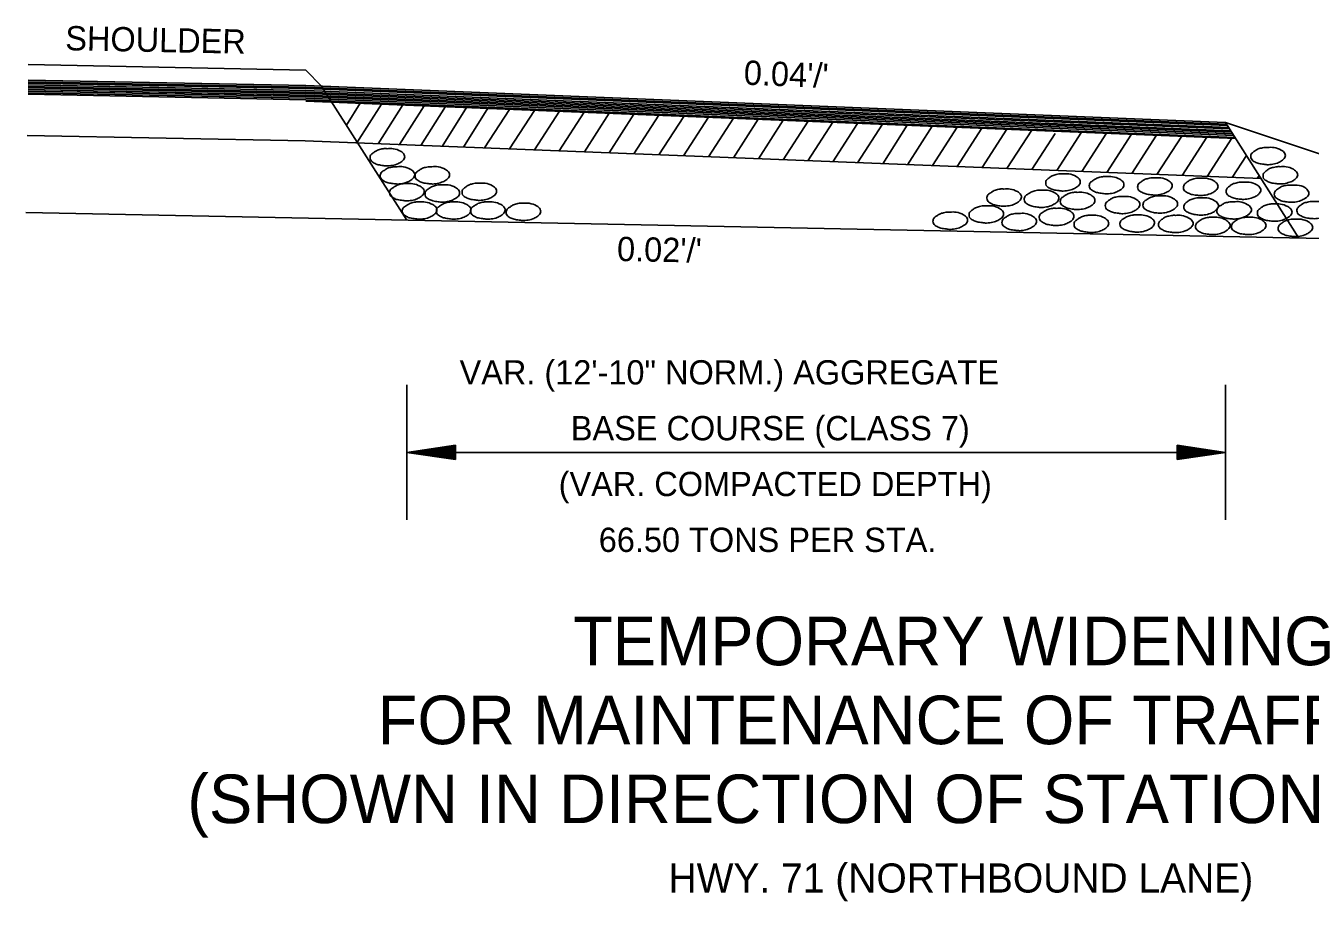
# Model space of a CAD drawing. Extents: x 634177 to 635904, y 289936 to 290970.
# Drawn here: x 635651.94 to 635683.67, y 290816.59 to 290838.23 of the extents above; entities that cross this region are included whole.
import ezdxf

# ---------------------------------------------------------------- set-up
doc = ezdxf.new("R2010")
doc.units = 0
doc.layers.add('Default', color=7, linetype='Continuous')

msp = doc.modelspace()

# ---------------------------------------------------------------- linework, layer by layer
at = {"layer": 'Default'}
for p, q in [((635651.994, 290836.882), (635658.855, 290836.747)), ((635651.994, 290836.84), (635658.855, 290836.703)), ((635651.994, 290836.808), (635658.855, 290836.67)), ((635651.994, 290836.767), (635658.855, 290836.628)), ((635651.994, 290836.727), (635658.855, 290836.586)), ((635658.855, 290836.747), (635681.573, 290835.834)), ((635659.246, 290836.733), (635661.351, 290833.421)), ((635651.994, 290836.689), (635658.855, 290836.55)), ((635651.994, 290836.65), (635658.855, 290836.512)), ((635651.994, 290836.611), (635658.855, 290836.474)), ((635651.994, 290836.568), (635658.855, 290836.432)), ((635651.994, 290836.53), (635658.855, 290836.395)), ((635658.855, 290836.703), (635681.601, 290835.789)), ((635658.855, 290836.67), (635681.619, 290835.761)), ((635658.855, 290836.628), (635681.649, 290835.714)), ((635658.855, 290836.586), (635681.674, 290835.675)), ((635658.855, 290836.55), (635681.703, 290835.629)), ((635658.855, 290836.512), (635681.724, 290835.596)), ((635658.855, 290836.474), (635681.752, 290835.551)), ((635658.855, 290836.432), (635681.777, 290835.512)), ((635658.855, 290836.395), (635681.806, 290835.466)), ((635658.855, 290836.362), (635681.823, 290835.44)), ((635659.857, 290835.772), (635660.198, 290836.311)), ((635660.114, 290835.329), (635660.722, 290836.289)), ((635660.639, 290835.308), (635661.248, 290836.269)), ((635661.166, 290835.287), (635661.776, 290836.243)), ((635661.693, 290835.267), (635662.301, 290836.226)), ((635662.224, 290835.245), (635662.827, 290836.203)), ((635662.748, 290835.225), (635663.354, 290836.184)), ((635663.27, 290835.204), (635663.889, 290836.159)), ((635663.885, 290835.18), (635664.503, 290836.134)), ((635664.501, 290835.156), (635665.121, 290836.111)), ((635665.115, 290835.131), (635665.732, 290836.088)), ((635665.734, 290835.106), (635666.349, 290836.063)), ((635666.344, 290835.083), (635666.958, 290836.036)), ((635666.96, 290835.058), (635667.574, 290836.013)), ((635667.575, 290835.034), (635668.188, 290835.986)), ((635668.183, 290835.009), (635668.802, 290835.963)), ((635668.804, 290834.986), (635669.419, 290835.941)), ((635669.416, 290834.961), (635670.028, 290835.916)), ((635670.032, 290834.937), (635670.645, 290835.888)), ((635670.641, 290834.913), (635671.259, 290835.863)), ((635671.256, 290834.889), (635671.87, 290835.84)), ((635671.875, 290834.864), (635672.484, 290835.813)), ((635672.484, 290834.841), (635673.097, 290835.792)), ((635681.573, 290835.834), (635683.385, 290832.979)), ((635681.573, 290835.834), (635701.326, 290829.249)), ((635651.974, 290835.514), (635658.835, 290835.379)), ((635673.103, 290834.816), (635673.711, 290835.767)), ((635673.714, 290834.792), (635674.325, 290835.74)), ((635674.332, 290834.768), (635674.943, 290835.717)), ((635674.943, 290834.743), (635675.556, 290835.692)), ((635675.557, 290834.719), (635676.17, 290835.668)), ((635676.172, 290834.695), (635676.785, 290835.644)), ((635676.79, 290834.67), (635677.363, 290835.564)), ((635677.402, 290834.646), (635678.013, 290835.593)), ((635678.021, 290834.622), (635678.632, 290835.568)), ((635678.64, 290834.598), (635679.251, 290835.543)), ((635679.259, 290834.573), (635679.869, 290835.518)), ((635679.878, 290834.549), (635680.488, 290835.493)), ((635680.497, 290834.524), (635681.107, 290835.469)), ((635658.835, 290835.379), (635682.453, 290834.447)), ((635681.117, 290834.5), (635681.726, 290835.444)), ((635681.736, 290834.475), (635682.088, 290835.022)), ((635682.355, 290834.451), (635682.403, 290834.526)), ((635651.936, 290833.608), (635690.566, 290832.836)), ((635661.351, 290829.353), (635661.351, 290826.017)), ((635681.573, 290829.353), (635681.573, 290826.017)), ((635662.551, 290827.865), (635661.351, 290827.685)), ((635662.551, 290827.505), (635662.551, 290827.865)), ((635680.373, 290827.865), (635681.573, 290827.685)), ((635680.373, 290827.865), (635680.373, 290827.505)), ((635661.351, 290827.685), (635681.573, 290827.685)), ((635662.551, 290827.505), (635661.351, 290827.685)), ((635662.551, 290827.835), (635661.551, 290827.685)), ((635662.551, 290827.535), (635661.551, 290827.685)), ((635662.551, 290827.804), (635661.758, 290827.685)), ((635662.551, 290827.566), (635661.758, 290827.685)), ((635662.551, 290827.774), (635661.958, 290827.685)), ((635662.551, 290827.596), (635661.958, 290827.685)), ((635662.551, 290827.744), (635662.161, 290827.685)), ((635662.551, 290827.627), (635662.161, 290827.685)), ((635662.551, 290827.713), (635662.361, 290827.685)), ((635662.551, 290827.657), (635662.361, 290827.685)), ((635680.373, 290827.835), (635681.373, 290827.685)), ((635680.373, 290827.804), (635681.166, 290827.685)), ((635680.373, 290827.774), (635680.966, 290827.685)), ((635680.373, 290827.743), (635680.763, 290827.685)), ((635680.373, 290827.713), (635680.563, 290827.685)), ((635680.373, 290827.505), (635681.573, 290827.685)), ((635680.373, 290827.626), (635680.763, 290827.685)), ((635680.373, 290827.566), (635681.166, 290827.685)), ((635680.373, 290827.535), (635681.373, 290827.685)), ((635680.373, 290827.596), (635680.966, 290827.685)), ((635680.373, 290827.657), (635680.563, 290827.685))]:
    msp.add_line(p, q, dxfattribs=at)
msp.add_lwpolyline([(635651.994, 290837.264), (635658.855, 290837.127), (635659.246, 290836.733)], dxfattribs=at)
for points in [[(635660.861, 290835.187), (635661.014, 290835.186), (635661.196, 290835.122), (635661.285, 290835.039), (635661.297, 290834.985), (635661.251, 290834.893), (635661.199, 290834.854), (635661.099, 290834.802), (635660.953, 290834.768), (635660.877, 290834.76), (635660.766, 290834.771), (635660.64, 290834.792), (635660.545, 290834.829), (635660.457, 290834.902), (635660.442, 290834.96), (635660.468, 290835.042), (635660.538, 290835.095), (635660.602, 290835.137), (635660.704, 290835.172), (635660.767, 290835.186), (635660.861, 290835.187)], [(635682.613, 290835.218), (635682.766, 290835.217), (635682.948, 290835.153), (635683.037, 290835.07), (635683.049, 290835.016), (635683.003, 290834.924), (635682.951, 290834.885), (635682.851, 290834.833), (635682.705, 290834.799), (635682.629, 290834.791), (635682.518, 290834.802), (635682.392, 290834.823), (635682.297, 290834.86), (635682.209, 290834.933), (635682.194, 290834.991), (635682.22, 290835.073), (635682.29, 290835.126), (635682.354, 290835.168), (635682.456, 290835.203), (635682.519, 290835.217), (635682.613, 290835.218)], [(635661.11, 290834.741), (635661.263, 290834.74), (635661.445, 290834.676), (635661.534, 290834.593), (635661.546, 290834.539), (635661.5, 290834.447), (635661.448, 290834.408), (635661.348, 290834.356), (635661.202, 290834.322), (635661.126, 290834.314), (635661.015, 290834.325), (635660.889, 290834.346), (635660.794, 290834.383), (635660.706, 290834.456), (635660.691, 290834.514), (635660.717, 290834.596), (635660.787, 290834.649), (635660.851, 290834.691), (635660.953, 290834.726), (635661.016, 290834.74), (635661.11, 290834.741)], [(635661.971, 290834.741), (635662.124, 290834.74), (635662.306, 290834.676), (635662.395, 290834.593), (635662.407, 290834.539), (635662.361, 290834.447), (635662.309, 290834.408), (635662.209, 290834.356), (635662.063, 290834.322), (635661.987, 290834.314), (635661.876, 290834.325), (635661.75, 290834.346), (635661.655, 290834.383), (635661.567, 290834.456), (635661.552, 290834.514), (635661.578, 290834.596), (635661.648, 290834.649), (635661.712, 290834.691), (635661.814, 290834.726), (635661.877, 290834.74), (635661.971, 290834.741)], [(635677.549, 290834.566), (635677.702, 290834.565), (635677.884, 290834.501), (635677.973, 290834.418), (635677.985, 290834.364), (635677.939, 290834.272), (635677.887, 290834.233), (635677.787, 290834.181), (635677.641, 290834.147), (635677.565, 290834.139), (635677.454, 290834.15), (635677.328, 290834.171), (635677.233, 290834.208), (635677.145, 290834.281), (635677.13, 290834.339), (635677.156, 290834.421), (635677.226, 290834.474), (635677.29, 290834.516), (635677.392, 290834.551), (635677.455, 290834.565), (635677.549, 290834.566)], [(635682.917, 290834.742), (635683.068, 290834.74), (635683.249, 290834.678), (635683.339, 290834.591), (635683.355, 290834.541), (635683.307, 290834.447), (635683.254, 290834.405), (635683.155, 290834.36), (635683.007, 290834.321), (635682.931, 290834.315), (635682.819, 290834.323), (635682.696, 290834.345), (635682.601, 290834.383), (635682.513, 290834.454), (635682.498, 290834.514), (635682.524, 290834.594), (635682.593, 290834.652), (635682.657, 290834.695), (635682.76, 290834.726), (635682.822, 290834.74), (635682.917, 290834.742)], [(635661.342, 290834.323), (635661.495, 290834.322), (635661.677, 290834.258), (635661.766, 290834.175), (635661.778, 290834.121), (635661.732, 290834.029), (635661.68, 290833.99), (635661.58, 290833.938), (635661.434, 290833.904), (635661.358, 290833.896), (635661.247, 290833.907), (635661.121, 290833.928), (635661.026, 290833.965), (635660.938, 290834.038), (635660.923, 290834.096), (635660.949, 290834.178), (635661.019, 290834.231), (635661.083, 290834.273), (635661.185, 290834.308), (635661.248, 290834.322), (635661.342, 290834.323)], [(635662.217, 290834.292), (635662.37, 290834.291), (635662.552, 290834.227), (635662.641, 290834.144), (635662.653, 290834.09), (635662.607, 290833.998), (635662.555, 290833.959), (635662.455, 290833.907), (635662.309, 290833.873), (635662.233, 290833.865), (635662.122, 290833.876), (635661.996, 290833.897), (635661.901, 290833.934), (635661.813, 290834.007), (635661.798, 290834.065), (635661.824, 290834.147), (635661.894, 290834.2), (635661.958, 290834.242), (635662.06, 290834.277), (635662.123, 290834.291), (635662.217, 290834.292)], [(635663.132, 290834.336), (635663.285, 290834.335), (635663.467, 290834.271), (635663.556, 290834.188), (635663.568, 290834.134), (635663.522, 290834.042), (635663.47, 290834.003), (635663.37, 290833.951), (635663.224, 290833.917), (635663.148, 290833.909), (635663.037, 290833.92), (635662.911, 290833.941), (635662.816, 290833.978), (635662.728, 290834.051), (635662.713, 290834.109), (635662.739, 290834.191), (635662.809, 290834.244), (635662.873, 290834.286), (635662.975, 290834.321), (635663.038, 290834.335), (635663.132, 290834.336)], [(635676.095, 290834.191), (635676.248, 290834.19), (635676.43, 290834.126), (635676.519, 290834.043), (635676.531, 290833.989), (635676.485, 290833.897), (635676.433, 290833.858), (635676.333, 290833.806), (635676.187, 290833.772), (635676.111, 290833.764), (635676, 290833.775), (635675.874, 290833.796), (635675.779, 290833.833), (635675.691, 290833.906), (635675.676, 290833.964), (635675.702, 290834.046), (635675.772, 290834.099), (635675.836, 290834.141), (635675.938, 290834.176), (635676.001, 290834.19), (635676.095, 290834.191)], [(635678.626, 290834.496), (635678.779, 290834.495), (635678.961, 290834.431), (635679.05, 290834.348), (635679.062, 290834.294), (635679.016, 290834.202), (635678.964, 290834.163), (635678.864, 290834.111), (635678.718, 290834.077), (635678.642, 290834.069), (635678.531, 290834.08), (635678.405, 290834.101), (635678.31, 290834.138), (635678.222, 290834.211), (635678.207, 290834.269), (635678.233, 290834.351), (635678.303, 290834.404), (635678.367, 290834.446), (635678.469, 290834.481), (635678.532, 290834.495), (635678.626, 290834.496)], [(635679.818, 290834.469), (635679.972, 290834.465), (635680.155, 290834.404), (635680.244, 290834.317), (635680.254, 290834.267), (635680.208, 290834.172), (635680.156, 290834.131), (635680.058, 290834.083), (635679.91, 290834.047), (635679.834, 290834.041), (635679.723, 290834.05), (635679.601, 290834.072), (635679.505, 290834.109), (635679.416, 290834.18), (635679.4, 290834.24), (635679.427, 290834.323), (635679.496, 290834.376), (635679.561, 290834.42), (635679.661, 290834.452), (635679.725, 290834.465), (635679.818, 290834.469)], [(635680.949, 290834.457), (635681.1, 290834.455), (635681.282, 290834.391), (635681.374, 290834.306), (635681.388, 290834.256), (635681.338, 290834.162), (635681.285, 290834.12), (635681.189, 290834.072), (635681.038, 290834.035), (635680.964, 290834.03), (635680.851, 290834.038), (635680.729, 290834.059), (635680.634, 290834.098), (635680.545, 290834.169), (635680.531, 290834.231), (635680.558, 290834.309), (635680.626, 290834.365), (635680.692, 290834.409), (635680.79, 290834.441), (635680.852, 290834.455), (635680.949, 290834.457)], [(635682.009, 290834.361), (635682.157, 290834.359), (635682.341, 290834.297), (635682.43, 290834.209), (635682.445, 290834.158), (635682.395, 290834.068), (635682.342, 290834.024), (635682.244, 290833.979), (635682.095, 290833.94), (635682.02, 290833.935), (635681.908, 290833.943), (635681.786, 290833.963), (635681.691, 290834.002), (635681.601, 290834.072), (635681.587, 290834.133), (635681.615, 290834.213), (635681.682, 290834.27), (635681.747, 290834.314), (635681.848, 290834.343), (635681.909, 290834.359), (635682.009, 290834.361)], [(635683.196, 290834.287), (635683.344, 290834.285), (635683.528, 290834.226), (635683.615, 290834.139), (635683.631, 290834.089), (635683.584, 290833.994), (635683.53, 290833.954), (635683.431, 290833.907), (635683.285, 290833.869), (635683.207, 290833.863), (635683.096, 290833.871), (635682.973, 290833.891), (635682.878, 290833.932), (635682.788, 290834.003), (635682.775, 290834.06), (635682.802, 290834.142), (635682.87, 290834.197), (635682.933, 290834.24), (635683.036, 290834.275), (635683.098, 290834.285), (635683.196, 290834.287)], [(635661.655, 290833.87), (635661.808, 290833.869), (635661.99, 290833.805), (635662.079, 290833.722), (635662.091, 290833.668), (635662.045, 290833.576), (635661.993, 290833.537), (635661.893, 290833.485), (635661.747, 290833.451), (635661.671, 290833.443), (635661.56, 290833.454), (635661.434, 290833.475), (635661.339, 290833.512), (635661.251, 290833.585), (635661.236, 290833.643), (635661.262, 290833.725), (635661.332, 290833.778), (635661.396, 290833.82), (635661.498, 290833.855), (635661.561, 290833.869), (635661.655, 290833.87)], [(635662.498, 290833.87), (635662.651, 290833.869), (635662.833, 290833.805), (635662.922, 290833.722), (635662.934, 290833.668), (635662.888, 290833.576), (635662.836, 290833.537), (635662.736, 290833.485), (635662.59, 290833.451), (635662.514, 290833.443), (635662.403, 290833.454), (635662.277, 290833.475), (635662.182, 290833.512), (635662.094, 290833.585), (635662.079, 290833.643), (635662.105, 290833.725), (635662.175, 290833.778), (635662.239, 290833.82), (635662.341, 290833.855), (635662.404, 290833.869), (635662.498, 290833.87)], [(635663.342, 290833.87), (635663.495, 290833.869), (635663.677, 290833.805), (635663.766, 290833.722), (635663.778, 290833.668), (635663.732, 290833.576), (635663.68, 290833.537), (635663.58, 290833.485), (635663.434, 290833.451), (635663.358, 290833.443), (635663.247, 290833.454), (635663.121, 290833.475), (635663.026, 290833.512), (635662.938, 290833.585), (635662.923, 290833.643), (635662.949, 290833.725), (635663.019, 290833.778), (635663.083, 290833.82), (635663.185, 290833.855), (635663.248, 290833.869), (635663.342, 290833.87)], [(635677.018, 290834.16), (635677.171, 290834.159), (635677.353, 290834.095), (635677.442, 290834.012), (635677.454, 290833.958), (635677.408, 290833.866), (635677.356, 290833.827), (635677.256, 290833.775), (635677.11, 290833.741), (635677.034, 290833.733), (635676.923, 290833.744), (635676.797, 290833.765), (635676.702, 290833.802), (635676.614, 290833.875), (635676.599, 290833.933), (635676.625, 290834.015), (635676.695, 290834.068), (635676.759, 290834.11), (635676.861, 290834.145), (635676.924, 290834.159), (635677.018, 290834.16)], [(635677.91, 290834.108), (635678.063, 290834.107), (635678.245, 290834.043), (635678.334, 290833.96), (635678.346, 290833.906), (635678.3, 290833.814), (635678.248, 290833.775), (635678.148, 290833.723), (635678.002, 290833.689), (635677.926, 290833.681), (635677.815, 290833.692), (635677.689, 290833.713), (635677.594, 290833.75), (635677.506, 290833.823), (635677.491, 290833.881), (635677.517, 290833.963), (635677.587, 290834.016), (635677.651, 290834.058), (635677.753, 290834.093), (635677.816, 290834.107), (635677.91, 290834.108)], [(635679.02, 290834.009), (635679.174, 290834.004), (635679.356, 290833.943), (635679.445, 290833.856), (635679.456, 290833.806), (635679.409, 290833.711), (635679.358, 290833.671), (635679.26, 290833.622), (635679.112, 290833.587), (635679.035, 290833.58), (635678.925, 290833.59), (635678.803, 290833.612), (635678.706, 290833.649), (635678.618, 290833.719), (635678.602, 290833.78), (635678.629, 290833.862), (635678.697, 290833.915), (635678.763, 290833.959), (635678.862, 290833.992), (635678.926, 290834.004), (635679.02, 290834.009)], [(635679.948, 290834.021), (635680.1, 290834.02), (635680.282, 290833.956), (635680.374, 290833.87), (635680.388, 290833.82), (635680.338, 290833.727), (635680.285, 290833.685), (635680.188, 290833.636), (635680.037, 290833.599), (635679.964, 290833.594), (635679.85, 290833.602), (635679.729, 290833.624), (635679.634, 290833.663), (635679.545, 290833.733), (635679.531, 290833.795), (635679.557, 290833.873), (635679.626, 290833.929), (635679.691, 290833.973), (635679.789, 290834.006), (635679.852, 290834.02), (635679.948, 290834.021)], [(635680.958, 290833.973), (635681.109, 290833.971), (635681.292, 290833.908), (635681.384, 290833.822), (635681.398, 290833.772), (635681.348, 290833.679), (635681.295, 290833.636), (635681.198, 290833.588), (635681.047, 290833.551), (635680.974, 290833.546), (635680.86, 290833.554), (635680.739, 290833.576), (635680.643, 290833.615), (635680.555, 290833.685), (635680.541, 290833.747), (635680.567, 290833.825), (635680.636, 290833.881), (635680.701, 290833.925), (635680.799, 290833.957), (635680.862, 290833.971), (635680.958, 290833.973)], [(635681.775, 290833.876), (635681.926, 290833.875), (635682.108, 290833.811), (635682.2, 290833.725), (635682.214, 290833.675), (635682.164, 290833.582), (635682.111, 290833.54), (635682.015, 290833.492), (635681.864, 290833.454), (635681.79, 290833.449), (635681.677, 290833.457), (635681.555, 290833.479), (635681.46, 290833.518), (635681.371, 290833.588), (635681.357, 290833.65), (635681.384, 290833.728), (635681.452, 290833.784), (635681.518, 290833.828), (635681.616, 290833.861), (635681.678, 290833.875), (635681.775, 290833.876)], [(635683.755, 290833.883), (635683.903, 290833.882), (635684.087, 290833.819), (635684.174, 290833.732), (635684.19, 290833.682), (635684.143, 290833.589), (635684.089, 290833.548), (635683.99, 290833.5), (635683.844, 290833.462), (635683.766, 290833.458), (635683.657, 290833.464), (635683.532, 290833.484), (635683.437, 290833.525), (635683.348, 290833.595), (635683.334, 290833.654), (635683.362, 290833.737), (635683.431, 290833.793), (635683.492, 290833.836), (635683.595, 290833.866), (635683.659, 290833.882), (635683.755, 290833.883)], [(635664.221, 290833.838), (635664.374, 290833.837), (635664.556, 290833.773), (635664.645, 290833.69), (635664.657, 290833.636), (635664.611, 290833.544), (635664.559, 290833.505), (635664.459, 290833.453), (635664.313, 290833.419), (635664.237, 290833.411), (635664.126, 290833.422), (635664, 290833.443), (635663.905, 290833.48), (635663.817, 290833.553), (635663.802, 290833.611), (635663.828, 290833.693), (635663.898, 290833.746), (635663.962, 290833.788), (635664.064, 290833.823), (635664.127, 290833.837), (635664.221, 290833.838)], [(635674.764, 290833.62), (635674.917, 290833.619), (635675.099, 290833.555), (635675.188, 290833.472), (635675.2, 290833.418), (635675.154, 290833.326), (635675.102, 290833.287), (635675.002, 290833.235), (635674.856, 290833.201), (635674.78, 290833.193), (635674.669, 290833.204), (635674.543, 290833.225), (635674.448, 290833.262), (635674.36, 290833.335), (635674.345, 290833.393), (635674.371, 290833.475), (635674.441, 290833.528), (635674.505, 290833.57), (635674.607, 290833.605), (635674.67, 290833.619), (635674.764, 290833.62)], [(635675.655, 290833.776), (635675.808, 290833.775), (635675.99, 290833.711), (635676.079, 290833.628), (635676.091, 290833.574), (635676.045, 290833.482), (635675.993, 290833.443), (635675.893, 290833.391), (635675.747, 290833.357), (635675.671, 290833.349), (635675.56, 290833.36), (635675.434, 290833.381), (635675.339, 290833.418), (635675.251, 290833.491), (635675.236, 290833.549), (635675.262, 290833.631), (635675.332, 290833.684), (635675.396, 290833.726), (635675.498, 290833.761), (635675.561, 290833.775), (635675.655, 290833.776)], [(635676.468, 290833.588), (635676.621, 290833.587), (635676.803, 290833.523), (635676.892, 290833.44), (635676.904, 290833.386), (635676.858, 290833.294), (635676.806, 290833.255), (635676.706, 290833.203), (635676.56, 290833.169), (635676.484, 290833.161), (635676.373, 290833.172), (635676.247, 290833.193), (635676.152, 290833.23), (635676.064, 290833.303), (635676.049, 290833.361), (635676.075, 290833.443), (635676.145, 290833.496), (635676.209, 290833.538), (635676.311, 290833.573), (635676.374, 290833.587), (635676.468, 290833.588)], [(635677.39, 290833.713), (635677.543, 290833.712), (635677.725, 290833.648), (635677.814, 290833.565), (635677.826, 290833.511), (635677.78, 290833.419), (635677.728, 290833.38), (635677.628, 290833.328), (635677.482, 290833.294), (635677.406, 290833.286), (635677.295, 290833.297), (635677.169, 290833.318), (635677.074, 290833.355), (635676.986, 290833.428), (635676.971, 290833.486), (635676.997, 290833.568), (635677.067, 290833.621), (635677.131, 290833.663), (635677.233, 290833.698), (635677.296, 290833.712), (635677.39, 290833.713)], [(635679.38, 290833.552), (635679.534, 290833.548), (635679.716, 290833.487), (635679.805, 290833.4), (635679.816, 290833.35), (635679.769, 290833.255), (635679.718, 290833.214), (635679.62, 290833.166), (635679.472, 290833.13), (635679.395, 290833.124), (635679.285, 290833.133), (635679.163, 290833.155), (635679.066, 290833.192), (635678.978, 290833.262), (635678.962, 290833.323), (635678.989, 290833.406), (635679.057, 290833.459), (635679.123, 290833.502), (635679.222, 290833.535), (635679.286, 290833.548), (635679.38, 290833.552)], [(635682.775, 290833.822), (635682.926, 290833.82), (635683.108, 290833.756), (635683.2, 290833.671), (635683.214, 290833.621), (635683.164, 290833.527), (635683.111, 290833.485), (635683.015, 290833.437), (635682.864, 290833.399), (635682.79, 290833.395), (635682.677, 290833.403), (635682.555, 290833.424), (635682.46, 290833.463), (635682.371, 290833.534), (635682.357, 290833.596), (635682.384, 290833.674), (635682.452, 290833.73), (635682.518, 290833.773), (635682.616, 290833.806), (635682.678, 290833.82), (635682.775, 290833.822)], [(635678.249, 290833.541), (635678.402, 290833.54), (635678.584, 290833.476), (635678.673, 290833.393), (635678.685, 290833.339), (635678.639, 290833.247), (635678.587, 290833.208), (635678.487, 290833.156), (635678.341, 290833.122), (635678.265, 290833.114), (635678.154, 290833.125), (635678.028, 290833.146), (635677.933, 290833.183), (635677.845, 290833.256), (635677.83, 290833.314), (635677.856, 290833.396), (635677.926, 290833.449), (635677.99, 290833.491), (635678.092, 290833.526), (635678.155, 290833.54), (635678.249, 290833.541)], [(635680.333, 290833.54), (635680.485, 290833.538), (635680.667, 290833.474), (635680.759, 290833.389), (635680.773, 290833.339), (635680.723, 290833.245), (635680.67, 290833.203), (635680.573, 290833.155), (635680.422, 290833.118), (635680.349, 290833.113), (635680.235, 290833.121), (635680.114, 290833.142), (635680.019, 290833.181), (635679.93, 290833.252), (635679.916, 290833.314), (635679.942, 290833.392), (635680.011, 290833.448), (635680.076, 290833.492), (635680.174, 290833.524), (635680.237, 290833.538), (635680.333, 290833.54)], [(635681.247, 290833.492), (635681.398, 290833.49), (635681.58, 290833.426), (635681.672, 290833.34), (635681.686, 290833.29), (635681.636, 290833.197), (635681.583, 290833.155), (635681.486, 290833.107), (635681.335, 290833.069), (635681.262, 290833.065), (635681.148, 290833.072), (635681.027, 290833.094), (635680.932, 290833.133), (635680.843, 290833.203), (635680.829, 290833.266), (635680.855, 290833.343), (635680.924, 290833.4), (635680.989, 290833.443), (635681.088, 290833.476), (635681.15, 290833.49), (635681.247, 290833.492)], [(635682.135, 290833.492), (635682.286, 290833.49), (635682.468, 290833.426), (635682.56, 290833.34), (635682.574, 290833.29), (635682.524, 290833.197), (635682.471, 290833.155), (635682.375, 290833.107), (635682.224, 290833.069), (635682.15, 290833.065), (635682.037, 290833.072), (635681.915, 290833.094), (635681.82, 290833.133), (635681.731, 290833.203), (635681.717, 290833.266), (635681.744, 290833.343), (635681.812, 290833.4), (635681.878, 290833.443), (635681.976, 290833.476), (635682.038, 290833.49), (635682.135, 290833.492)], [(635683.288, 290833.443), (635683.439, 290833.442), (635683.621, 290833.378), (635683.713, 290833.292), (635683.727, 290833.242), (635683.677, 290833.149), (635683.624, 290833.107), (635683.528, 290833.058), (635683.377, 290833.021), (635683.303, 290833.016), (635683.19, 290833.024), (635683.068, 290833.046), (635682.973, 290833.085), (635682.884, 290833.155), (635682.87, 290833.217), (635682.897, 290833.295), (635682.965, 290833.351), (635683.031, 290833.395), (635683.129, 290833.428), (635683.191, 290833.442), (635683.288, 290833.443)]]:
    msp.add_spline(points, degree=3, dxfattribs=at)

# ---------------------------------------------------------------- texts
for s, rotation, p in [('SHOULDER', 358.8542, (635652.909, 290837.62)), ("0.04'/'", 357.7077, (635669.664, 290836.77)), ("0.02'/'", 358.8543, (635666.537, 290832.413))]:
    msp.add_text(s, height=0.6, rotation=rotation, dxfattribs=at).set_placement(p)
for s, height, p in [('VAR. (12\'-10" NORM.) AGGREGATE', 0.6, (635662.652, 290829.362)), ('BASE COURSE (CLASS 7)', 0.6, (635665.4, 290827.983)), ('(VAR. COMPACTED DEPTH)', 0.6, (635665.1, 290826.604)), ('66.50 TONS PER STA.', 0.6, (635666.09, 290825.225)), ('TEMPORARY WIDENING ', 1.2, (635665.456, 290822.426)), ('FOR MAINTENANCE OF TRAFFIC', 1.2, (635660.631, 290820.476)), ('(SHOWN IN DIRECTION OF STATIONING)', 1.2, (635655.927, 290818.526)), ('HWY. 71 (NORTHBOUND LANE)', 0.72, (635667.813, 290816.811))]:
    msp.add_text(s, height=height, dxfattribs=at).set_placement(p)

doc.saveas('drawing.dxf')
